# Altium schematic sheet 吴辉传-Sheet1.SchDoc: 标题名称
size A4; Organization: 单位信息; Address1: 考生班别; Address2: 姓名; Address3: 学号
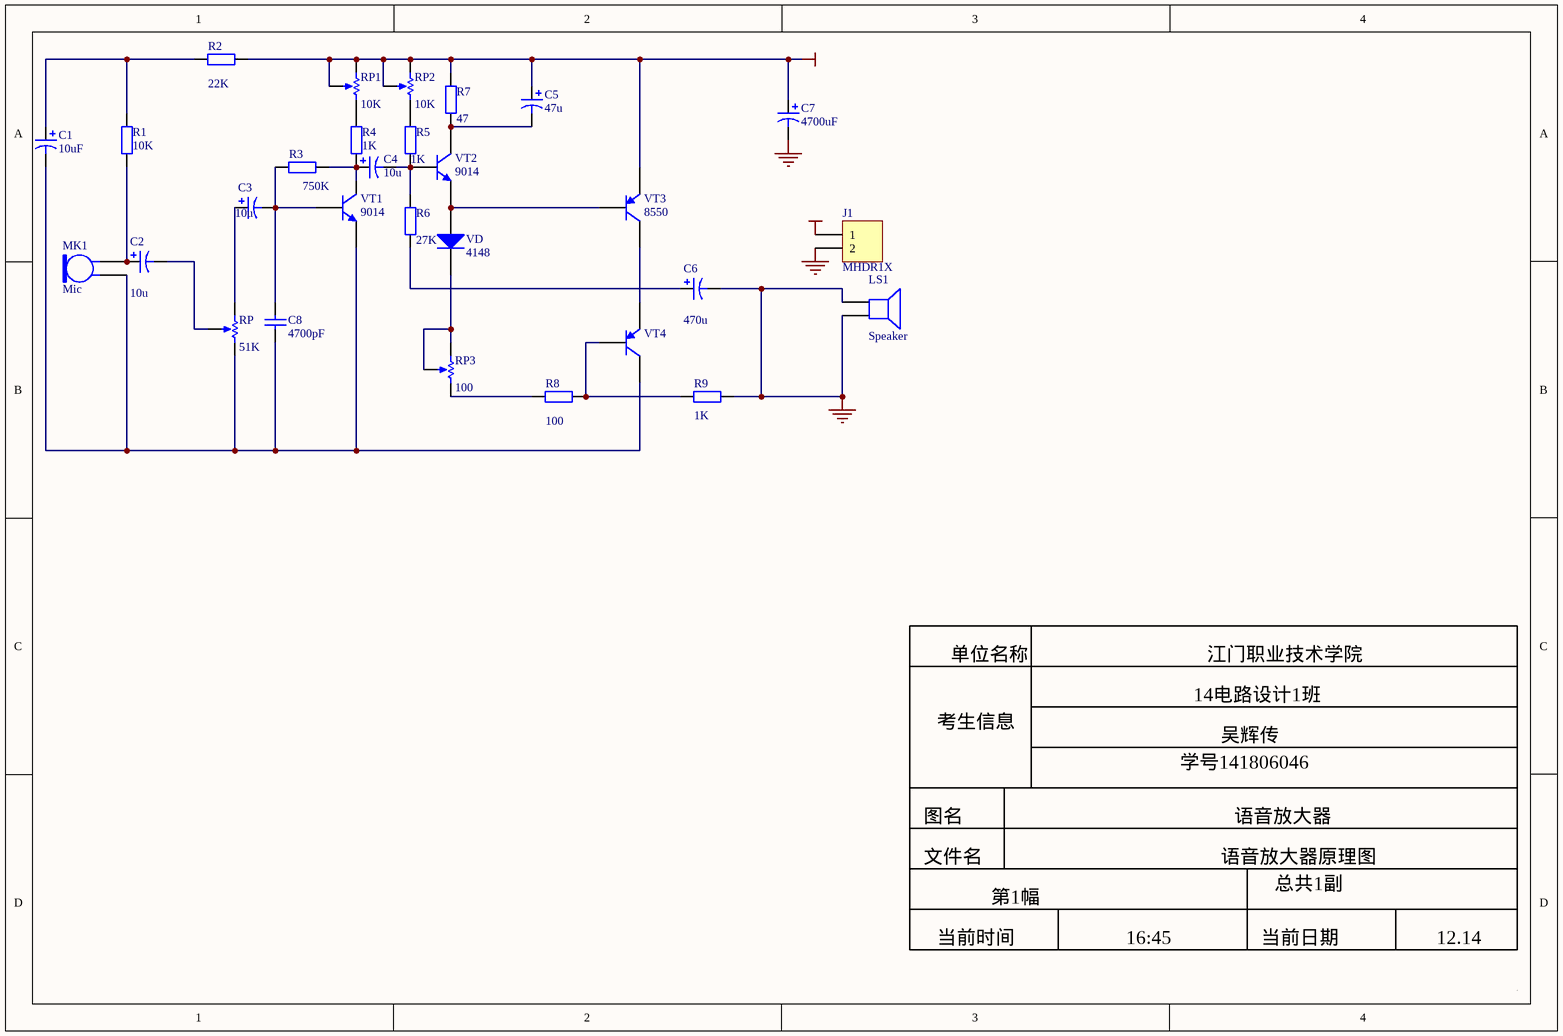
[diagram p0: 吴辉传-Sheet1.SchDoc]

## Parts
C1  10uF  [RB7.6-15]
C2  value 10u  [RB7.6-15]  (hidden comment: Cap Pol1)
C3  value 10u  [RB7.6-15]  (hidden comment: Cap Pol1)
C4  value 10u  [RB7.6-15]  (hidden comment: Cap Pol1)
C5  value 47u  [RB7.6-15]  (hidden comment: Cap Pol1)
C6  value 470u  [RB7.6-15]  (hidden comment: Cap Pol1)
C7  value 4700uF  [RB7.6-15]  (hidden comment: Cap Pol1)
C8  value 4700pF  [RAD-0.3]  (hidden comment: Cap)
J1  MHDR1X  [HDR1X2H]
LS1  Speaker  [PIN2]
MK1  Mic  [PIN2]
R1  value 10K  [AXIAL-0.4]  (hidden comment: Res2)
R2  value 22K  [AXIAL-0.4]  (hidden comment: Res2)
R3  value 750K  [AXIAL-0.4]  (hidden comment: Res2)
R4  value 1K  [AXIAL-0.4]  (hidden comment: Res2)
R5  value 1K  [AXIAL-0.4]  (hidden comment: Res2)
R6  value 27K  [AXIAL-0.4]  (hidden comment: Res2)
R7  value 47  [AXIAL-0.4]  (hidden comment: Res2)
R8  value 100  [AXIAL-0.4]  (hidden comment: Res2)
R9  value 1K  [AXIAL-0.4]  (hidden comment: Res2)
RP  value 51K  [PCBComponent_1]  (hidden comment: RPot)
RP1  value 10K  [PCBComponent_1]  (hidden comment: RPot)
RP2  value 10K  [PCBComponent_1]  (hidden comment: RPot)
RP3  value 100  [PCBComponent_1]
VD  4148  [DIO10.46-5.3x2.8]
VT1  9014  [BCY-W3/E4]
VT2  9014  [BCY-W3/E4]
VT3  8550  [BCY-W3/E4]
VT4  8550  [BCY-W3/E4]  (value not drawn)

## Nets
GND: C6.2 C7.2 J1.2 LS1.1 LS1.2 R9.2
VCC: C5.1 C7.1 J1.1 R2.2 R7.1 RP1.1(TOP) RP1.3(TAP) RP2.1(TOP) RP2.3(TAP) VT3.1(E)
NetC1_1: C1.1 R1.1 R2.1
NetC1_2: C1.2 C8.2 MK1.1 RP.2(BOT) VT1.1(E) VT4.3(C)
NetC2_1: C2.1 MK1.2 R1.2
NetC2_2: C2.2 RP.3(TAP)
NetC3_1: C3.1 RP.1(TOP)
NetC3_2: C3.2 C8.1 R3.1 VT1.2(B)
NetC4_1: C4.1 R3.2 R4.2 VT1.3(C)
NetC4_2: C4.2 R5.2 R6.1 VT2.2(B)
NetC5_2: C5.2 R7.2 VT2.3(C)
NetC6_1: C6.1 R6.2
NetR4_1: R4.1 RP1.2(BOT)
NetR5_1: R5.1 RP2.2(BOT)
NetR8_1: R8.1 RP3.2(BOT)
NetR8_2: R8.2 R9.1 VT4.2(B)
NetRP3_1: RP3.1(TOP) RP3.3(TAP) VD.2(K)
NetVD_1: VD.1(A) VT2.1(E) VT3.2(B)
NetVT3_3: VT3.3(C) VT4.1(E)

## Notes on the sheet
- 单位名称
- 14电路设计1班
- 江门职业技术学院
- 考生信息
- 学号141806046
- 吴辉传
- 图名
- 语音放大器
- 文件名
- 第1幅
- 语音放大器原理图
- 总共1副
- 当前时间
- 16:45
- 当前日期
- 12.14

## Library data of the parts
C1-C7 = Cap Pol1: Polarized Capacitor (Radial)
C8 = Cap: Capacitor
J1 = Header 2H: Header, 2-Pin, Right Angle
LS1 = Speaker: Loudspeaker
MK1 = Mic2: Microphone
R1-R9 = Res2: Resistor
RP RP1-RP3 = RPot: Potentiometer; Sim Note: Enter the Resistance value and the set point into parameter fields.; Set Position: 0.5
VD = Diode 1N4001: 1 Amp General Purpose Rectifier
VT1 VT2 = 2N3904: NPN General Purpose Amplifier
VT3 VT4 = 2N3906: PNP General Purpose Amplifier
